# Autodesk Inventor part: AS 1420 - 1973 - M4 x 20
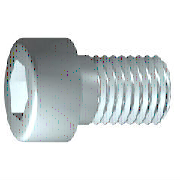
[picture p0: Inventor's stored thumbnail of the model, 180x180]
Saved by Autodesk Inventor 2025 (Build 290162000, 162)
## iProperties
Created: 2024-01
Part Number: AS 1420 - 1973 - M4 x 20
Material: Acciaio, Dolce
Description: Viti con esagono incassato metriche ISO
Document SubType Name: Modeling
Standard: AS 1420 - 1973
Designer: R5800u
Standards Organization: AS
Language: it-IT
Size Designation: M4 x 20
Categories: <MemberInstance><Categories><Category DisplayName="Elementi di fissaggio" InternalName="e4da775c-781d-43d5-af7c-5136215cf5a6" Mnemonic="FSTN"><Category DisplayN
Density: 7.85 g/cm^3
Appearance: Semilucidato
IsCustomPart: 0
Author: R5800u
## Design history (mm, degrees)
body "Solid1"
workplane "Work Plane1"
fillet "Fillet2" dims "d30" = 0.1 (= R)
revolve "Corpo" stored, may be unused: angle "d10" = 90 deg
sketch "Schizzo2"
  geometry: L1 (0, -4.9)-(0, 4.9) reference; L2 (-4.9, 0)-(4.9, 0) reference; L3 (1.732, 0)-(0.866, -1.5); L4 (0.866, -1.5)-(-0.866, -1.5); L5 (-0.866, -1.5)-(-1.732, 0); L6 (-1.732, 0)-(-0.866, 1.5); L7 (-0.866, 1.5)-(0.866, 1.5); L8 (0.866, 1.5)-(1.732, 0); 2 further points
  constraints: 12 end point, 1 coincident, 1 horizontal alignment, 1 point on line, 12 other
extrude "Intaglio" join sketch "Schizzo2" stored distance "d11" = 10; taper "d12" = 0 deg
fillet "Raccordo1" dims "d17" = 0.4 (= RR)
feature "Filettatura" dims "d13" = 14 (= GEL), "d14" = 0
chamfer "Smusso1" distance "d15" = 0.42941 (= -0.5 x SPD + 0.5 x GD); stored, may be unused: second distance "d16" = 0.42941 (= GUL), angle "d27" = 45 deg
sketch "Schizzo1"
  geometry: L1 (-1, 0)-(20, 0); L2 (20, 0)-(20, 2); L3 (20, 2)-(6, 2); L4 (6, 2)-(5.57, 2); L5 (5.57, 2)-(0, 2); L6 (0, 2)-(0, 3.5); L7 (0, 3.5)-(-4, 3.5); L8 (-4, 3.5)-(-4, 1.732); L9 (-4, 1.732)-(-2, 1.732); L10 (-2, 1.732)-(-1, 0); L11 (-8.8, 0)-(24.8, 0) reference; L12 (0, -0.7)-(0, 4.2) reference; L13 (6, 2)-(0, 2)
  constraints: 22 end point, 6 parallel, 2 collinear, 2 perpendicular, 1 horizontal, 1 point on line
  dimensions: "d1" = 14 distance from line of L3.end L2 (= GEL); "d2" = 0.42952 distance of L4.end L3.end (computed from GAL); "d3" = 4 distance between parallel lines of L8 L6 (= KOH); "d4" = 2 distance of L8.end L9.end (= INTI); "d5" = 60 deg angle of L10 L1; "d6" = 4 diameter of L3 L1 (= GD); "d7" = 4 diameter of L5 L1 (= BDM); "d8" = 3.4641 diameter of L9 L1 (= 1.1547 x SW); "d9" = 7 diameter of L7 L1 (= KOD); "d26" = 20 distance between parallel lines of L12 L2 (= NLG)
other parameters: "GD" = 4 (= NND) [user parameter; used in 2 equation terms], "NLG" = 20 [user parameter; used in 1 equation term], "GEL" = 14 [user parameter; used in 2 equation terms], "KOD" = 7 [user parameter; used in 1 equation term], "KOH" = 4 (= NND) [user parameter; used in 1 equation term], "INTI" = 2 [user parameter; used in 1 equation term], "GAL" = 0.42941 (= 0.61345 x PTC) [user parameter; used in 1 equation term], "GUL" = 0.42941 (= 0.61345 x PTC) [user parameter; used in 1 equation term], "BDM" = 4 (= NND) [user parameter; used in 1 equation term], "SW" = 3 [user parameter; used in 2 equation terms], "RR" = 0.4 (= 0.1 x NND) [user parameter; used in 1 equation term], "SPD" = 3.14117 (= NND - 1.2269 x PTC) [user parameter; used in 1 equation term], "d19" = 0, "d28" = 0, "d29" = 0, "R" = 0.1 [user parameter; used in 1 equation term], "PHH" = 0.13 [user parameter], "GD1" = 3.14117 (= THREADDIA - 1.2269 x PTC) [user parameter], "THREADDIA" = 4 [user parameter; used in 1 equation term], "FAWI" = 45 deg [user parameter], "TPU" = 14.28571 (computed from PTC) [user parameter], "PTC" = 0.7 [user parameter; used in 5 equation terms], "KOH1" = 3.6 [user parameter], "NND" = 4 [user parameter; used in 5 equation terms], "TOA" = 30 deg [user parameter], "E0" = 3.465 (= 1.155 x SW) [user parameter]
